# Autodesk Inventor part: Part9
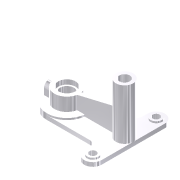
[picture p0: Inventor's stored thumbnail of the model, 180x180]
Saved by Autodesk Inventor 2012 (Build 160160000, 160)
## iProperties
Shininess: 77.0
Length Units: 11269
Angle Units: 11279
Time Units: 11290
Mass Units: 11283
Length Display Precision: 3
Angle Display Precision: 2
Created: 2001-12
Part Number: Part9
Document SubType Name: Modeling
Density: 1 g/cm^3
Material: Default
Density: 0.0
Volumn: 0.0
Area: 0.0
PropertySet Name: Model Information
Control State: 0
Master: False
Checked Out: False
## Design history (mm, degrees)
sketch "Sketch1"
  geometry: L1 (46.121, -53.4)-(46.121, 56.6); L2 (16.121, 56.6)-(16.121, 36.6); L3 (16.121, 36.6)-(-68.879, 36.6); L4 (-68.879, -33.4)-(16.121, -33.4); L5 (16.121, -33.4)-(16.121, -53.4); A1 r 15 centre (31.121, 56.6) between (46.121, 56.6) and (16.121, 56.6); A2 r 35 centre (-68.879, 1.6) between (-68.879, 36.6) and (-68.879, -33.4); A3 r 15 centre (31.121, -53.4) between (16.121, -53.4) and (46.121, -53.4)
  constraints: 10 end point, 6 point on circle, 5 tangent, 3 centre point, 3 parallel, 2 equal length, 1 equal radius, 1 perpendicular, 1 vertical
  dimensions: "d0" = 15 radius of A1; "d1" = 110 distance of L1.start L1.end; "d2" = 100 horizontal distance of A3.centre A2.centre; "d3" = 35 radius of A2
extrude "Extrusion1" new body sketch "Sketch1" distance "d4" = 7; taper "d5" = 0 deg
sketch "Sketch2"
  geometry: C1 r 10 at (31.121, 56.6); C2 r 10 at (31.121, -53.4); C3 r 35 at (-68.879, 1.6); A1 r 35 centre (-68.879, 1.6) between (-68.879, 36.6) and (-68.879, -33.4) reference; A2 r 15 centre (31.121, 56.6) between (46.121, 56.6) and (16.121, 56.6) reference; A3 r 15 centre (31.121, -53.4) between (16.121, -53.4) and (46.121, -53.4) reference
  constraints: 3 centre point, 3 concentric, 2 equal radius
  dimensions: "d45" = 20 diameter of C1
extrude "Extrusion2" join sketch "Sketch2" distance "d6" = 3; taper "d7" = 0 deg
sketch "Sketch3"
  geometry: C1 r 22 at (0, 0); 1 further point
  constraints: 1 centre point, 1 coincident
  dimensions: "d8" = 44 diameter of C1
extrude "Extrusion3" join sketch "Sketch3" distance "d9" = 23; taper "d10" = 0 deg
sketch "Sketch4"
  geometry: L1 (46.121, 56.6)-(46.121, -53.4) reference; L2 (-68.879, 36.6)-(16.121, 36.6) reference; C1 r 15 at (31.121, 1.6)
  constraints: 1 centre point
  dimensions: "d11" = 30 diameter of C1; "d12" = 15 distance from line of L1 C1.centre; "d13" = 35 distance from line of L2 C1.centre
extrude "Extrusion4" join sketch "Sketch4" distance "d14" = 88; taper "d15" = 0 deg
workplane "Work Plane1"
sketch "Sketch5"
  geometry: L1 (22, 33.1)-(85, 48); L2 (0, 7)-(35, 7) reference; L3 (85, 0)-(85, 7) reference; L4 (115, 0)-(115, 7) reference; L5 (115, 0)-(85, 0) reference
  constraints: 2 end point
  dimensions: "d17" = 26.1 distance from line of L2 L1.start; "d18" = 63 distance from line of L3 L1.start; "d19" = 30 distance from line of L4 L1.end; "d20" = 48 distance from line of L5 L1.end
feature "Rib1" sketch "Sketch5" dims "d21" = 1, "d22" = 8
workplane "Work Plane2"
workplane "Work Plane3"
sketch "Sketch7"
  geometry: L1 (10, 0)-(10, 10); L2 (-10, 10)-(-10, 0); L3 (-10, 0)-(10, 0); L4 (55, -10)-(55, -3) reference; A1 r 10 centre (0, 10) between (10, 10) and (-10, 10); 2 further points
  constraints: 6 end point, 2 point on circle, 2 tangent, 1 centre point, 1 parallel, 1 perpendicular, 1 vertical
  dimensions: "d30" = 10 radius of A1; "d34" = 55 distance from line of L4 A1.centre; "d35" = 10 distance of L1.start L1.end
extrude "Extrusion6" join sketch "Sketch7" stored distance "d36" = 88; taper "d37" = 0 deg
sketch "Sketch8"
  geometry: C1 r 10 at (0, 0) reference
hole "Hole1" sketch "Sketch8" at (0, 0) diameter "d38" = 12; stored, may be unused: countersink angle "d42" = 82 deg, drill point angle "d44" = 118 deg; dims "d39" = 6, "d40" = 4, "d41" = 2, "d43" = 8
mirror "Mirror1"
sketch "Sketch9"
  geometry: C1 r 10 at (0, 0)
  constraints: 1 centre point
hole "Hole2" sketch "Sketch9" at (0, 0) diameter "d52" = 18; stored, may be unused: drill point angle "d47" = 118 deg, countersink angle "d48" = 82 deg; dims "d46" = 6, "d49" = 2, "d50" = 4, "d51" = 8
sketch "Sketch10"
  geometry: C1 r 10 at (0, 0)
  constraints: 1 centre point
hole "Hole3" sketch "Sketch10" at (0, 0) diameter "d59" = 24; stored, may be unused: drill point angle "d54" = 118 deg, countersink angle "d55" = 82 deg; dims "d53" = 6, "d56" = 8, "d57" = 30, "d58" = 8
sketch "Sketch11"
  geometry: C1 r 10 at (0, 0)
  constraints: 1 centre point
hole "Hole4" sketch "Sketch11" at (0, 0) diameter "d66" = 10; stored, may be unused: drill point angle "d61" = 0 deg, countersink angle "d62" = 82 deg; dims "d60" = 6, "d63" = 2, "d64" = 4, "d65" = 8
fillet "Fillet1" dims "d67" = 10
body "Solid1"
other parameters: "d16" = -35, "d29" = -8
